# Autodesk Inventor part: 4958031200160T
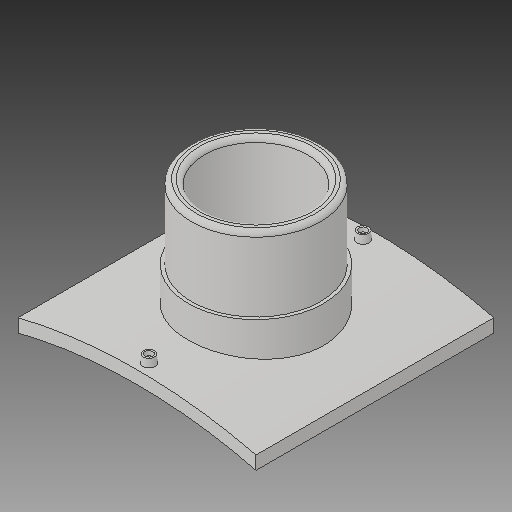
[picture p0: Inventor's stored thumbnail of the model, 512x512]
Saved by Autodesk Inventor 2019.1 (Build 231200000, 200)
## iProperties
Created: 2017-10
Part Number: 4958031200160T
Material: Generic
Description: PLASSON BRANCH SADDLE  1200x160
Document SubType Name: Modeling
Designer: KIM
Mass: 2754.05 g
Surface Area: 3037.44 cm^2
Volume: 2754.05 cm^3
Density: 1 g/cm^3
Appearance: Default
Author: KIM
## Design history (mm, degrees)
derived "495803.ipt"
feature "Solid1::495803.ipt"
tag "TaggingFeature1"
body "Solid1"
other parameters: "d1" = 16, "d2" = 295, "d3" = 295, "d4" = 0, "d12" = 625.6, "d13" = 14, "d14" = 132.75, "d16" = 5 deg, "d18" = 4, "d19" = 14, "d20" = 0, "d21" = 3, "d22" = 0, "d23" = 747, "d24" = 168, "d25" = 16, "d26" = 128, "d28" = 0, "d29" = 9.6, "d31" = 0, "d32" = 65.5, "d33" = 0, "d34" = 12, "d37" = 91.7, "d38" = 0, "d39" = 6, "B_" = 295, "H_" = 131, "L_" = 295, "x_" = 16, "D_" = 16
